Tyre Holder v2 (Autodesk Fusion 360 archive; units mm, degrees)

design "Tyre Holder" references "Small tyre"
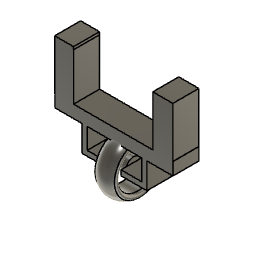
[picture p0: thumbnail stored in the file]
sketch "Sketch1" plane through (0, 0, 0) normal (0, 1, 0) x axis (1, 0, 0)
  line L1 (26.7266, -33.9417) -> (19.4439, -33.9417)
  line L2 (26.7266, -15.4922) -> (26.7266, -33.9417)
  line L3 (19.4439, -15.4922) -> (26.7266, -15.4922)
  line L4 (19.4439, -33.9417) -> (19.4439, -15.4922)
  horizontal L1
  vertical L2
  horizontal L3
  vertical L4
extrude "Extrude1" new body sketch "Sketch1" along normal blind 10
sketch "Sketch2" plane through (0, 0, 0) normal (0, 1, 0) x axis (1, 0, 0)
  line L1 (65, -35.1686) -> (57.2809, -35.1686)
  line L2 (65, -15) -> (65, -35.1686)
  line L3 (57.2809, -15) -> (65, -15)
  line L4 (57.2809, -35.1686) -> (57.2809, -15)
  horizontal L1
  vertical L2
  horizontal L3
  vertical L4
extrude "Extrude2" new body sketch "Sketch2" along normal blind 10
move_face "MoveFace1"
sketch "Sketch3" plane through (0, 0, 0) normal (0, 1, 0) x axis (1, 0, 0)
  line L1 (65.0384, -15.7821) -> (19.5015, -15.7821)
  line L2 (65.0384, -10.957) -> (65.0384, -15.7821)
  line L3 (19.5015, -10.957) -> (65.0384, -10.957)
  line L4 (19.5015, -15.7821) -> (19.5015, -10.957)
  horizontal L1
  vertical L2
  horizontal L3
  vertical L4
extrude "Extrude3" add sketch "Sketch3" along normal blind 10
sketch "Sketch4" plane through (0, 0, 0) normal (0, 1, 0) x axis (1, 0, 0)
  line L1 (26.7138, -34.9681) -> (19.4586, -34.9681)
  line L2 (26.7138, -33.3054) -> (26.7138, -34.9681)
  line L3 (19.4586, -33.3054) -> (26.7138, -33.3054)
  line L4 (19.4586, -34.9681) -> (19.4586, -33.3054)
  horizontal L1
  vertical L2
  horizontal L3
  vertical L4
extrude "Extrude4" add sketch "Sketch4" along normal blind 10
sketch "Sketch5" plane through (0, 0, 0) normal (0, 1, 0) x axis (1, 0, 0)
  line L1 (32, -11) -> (30, -11)
  line L2 (32, -1) -> (32, -11)
  line L3 (30, -1) -> (32, -1)
  line L4 (30, -11) -> (30, -1)
  horizontal L1
  vertical L2
  horizontal L3
  vertical L4
extrude "Extrude5" add sketch "Sketch5" along normal blind 10
sketch "Sketch6" plane through (0, 0, 0) normal (0, 1, 0) x axis (1, 0, 0)
  line L1 (53, -11) -> (55, -11)
  line L2 (53, -1) -> (53, -11)
  line L3 (55, -1) -> (53, -1)
  line L4 (55, -11) -> (55, -1)
  horizontal L1
  vertical L2
  horizontal L3
  vertical L4
extrude "Extrude6" add sketch "Sketch6" along normal blind 10
sketch "Sketch7" plane through (0, 0, 0) normal (0, 1, 0) x axis (1, 0, 0)
  line L1 (40, -3) -> (32, -3)
  line L2 (40, -1) -> (40, -3)
  line L3 (32, -1) -> (40, -1)
  line L4 (32, -3) -> (32, -1)
  horizontal L1
  vertical L2
  horizontal L3
  vertical L4
extrude "Extrude7" add sketch "Sketch7" along normal blind 10
sketch "Sketch8" plane through (0, 0, 0) normal (0, 1, 0) x axis (1, 0, 0)
  line L1 (53, -3) -> (45, -3)
  line L2 (53, -1) -> (53, -3)
  line L3 (45, -1) -> (53, -1)
  line L4 (45, -3) -> (45, -1)
  horizontal L1
  vertical L2
  horizontal L3
  vertical L4
extrude "Extrude8" add sketch "Sketch8" along normal blind 10
sketch "Sketch9" plane through (0, 0, 0) normal (0, 1, 0) x axis (1, 0, 0)
  line L1 (40, -3) -> (39, -3)
  line L2 (40, -1) -> (40, -3)
  line L3 (39, -1) -> (40, -1)
  line L4 (39, -3) -> (39, -1)
  horizontal L1
  vertical L2
  horizontal L3
  vertical L4
extrude "Extrude9" cut sketch "Sketch9" along normal blind 10
component_insert "Component Insert"

design "Small tyre"
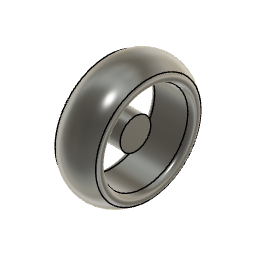
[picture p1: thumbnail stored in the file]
sketch "Sketch1" plane through (0, 0, 0) normal (1, 0, 0) x axis (0, 1, 0)
  circle C1 centre (24.9666, 12.7062) radius 12.6513
extrude "Extrude1" new body sketch "Sketch1" along normal blind 10
hole "Hole1" HoleDepth 10 HoleDiameter 10 TipAngle 118 CBDepth 1 CBDiameter 16
delete_face "DeleteFace1"
fillet "Fillet1" radius 5.5
fillet "Fillet2" radius 1
fillet "Fillet3" radius 1
sketch "Sketch2" plane through (0, 0, 0) normal (1, 0, 0) x axis (0, 1, 0)
  circle C1 centre (25, 13) radius 2.8284
extrude "Extrude2" new body sketch "Sketch2" along normal blind 5
sketch "Sketch3" plane through (0, 0, 0) normal (1, 0, 0) x axis (0, 1, 0)
sketch "Sketch4" plane through (0, 0, 0) normal (1, 0, 0) x axis (0, 1, 0)
move_face "MoveFace1"
move_face "MoveFace2"
move_face "MoveFace3"
move_face "MoveFace4"
move_face "MoveFace5"
move_face "MoveFace6"
fillet "Fillet4" radius 5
